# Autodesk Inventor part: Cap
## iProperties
Shininess: 77.0
Angle Display Precision: 2
Document Length Units: 11269
Document Angle Units: 11279
Document Time Units: 11290
Document Mass Units: 11283
Document Length Units Precision: 3
Document Angle Units Precision: 2
Created: 2002-02
Part Number: Cap
Document SubType Name: Modeling
Designer: ***
Density: 0.0
Volumn: 0.0
Area: 0.0
PropertySet Name: Model Information
Control State: 0
Master: False
Checked Out: False
Author: ***
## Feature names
1. Extrusion1
2. Extrusion2
3. Hole1
4. Hole2
5. Mirror1
6. Hole3
